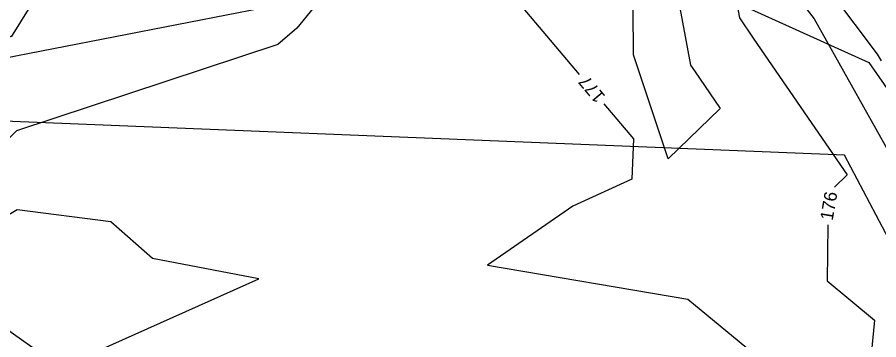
# Model space of a CAD drawing. Extents: x 2086416 to 2115205, y 575507 to 632762.
# Drawn here: x 2111423.3 to 2111557.3, y 581547.6 to 581597.8 of the extents above; entities that cross this region are included whole.
import ezdxf

# ---------------------------------------------------------------- set-up
doc = ezdxf.new("R2010")
doc.units = 0
for name, color, linetype in [('DTM Contours Major', 7, 'Continuous'), ('DTM Contours Minor', 7, 'Continuous'), ('DTM Contours Minor Text', 7, 'Continuous'), ('Exist Hydrographic FEMA Cross Section', 7, 'Continuous'), ('Exist Vegetation Woods Line', 7, 'Continuous')]:
    doc.layers.add(name, color=color, linetype=linetype)

msp = doc.modelspace()

# ---------------------------------------------------------------- linework, layer by layer
at = {"layer": 'DTM Contours Major'}
msp.add_lwpolyline([(2111534.94, 581633.7), (2111534.95, 581633.69), (2111540.69, 581621.59), (2111540.75, 581620.7), (2111543.07, 581605.02), (2111543.15, 581604.73), (2111546.21, 581598.92), (2111547.25, 581597.53), (2111560.71, 581573.54), (2111564.82, 581569.8), (2111569.33, 581557.68), (2111570.48, 581553.11), (2111574.03, 581543.19)], dxfattribs=at)
at = {"layer": 'DTM Contours Minor'}
for points in [[(2111512.9, 581612.94), (2111502.54, 581616.24), (2111495.93, 581612.32), (2111495.05, 581609.68), (2111493.14, 581612.37), (2111486.49, 581613.5), (2111483.67, 581613.74), (2111483.2, 581613.6), (2111482.12, 581613.44), (2111472.63, 581599.99), (2111469.34, 581599.17), (2111466.84, 581596.07), (2111463.88, 581593.54), (2111423.2, 581580.1), (2111421.17, 581578.02), (2111413.92, 581573.83), (2111415.71, 581582.77), (2111413.83, 581586.35), (2111407.09, 581599.12), (2111404.08, 581600.93), (2111385.48, 581590.71), (2111395.03, 581602.54), (2111389.52, 581602.88), (2111380.32, 581601.49)], [(2111438.65, 581609.75), (2111436.08, 581609.42), (2111428.87, 581608.47), (2111427.89, 581607.98), (2111428.68, 581604.78), (2111428.43, 581604.52), (2111422.37, 581594.71), (2111411.16, 581598.81), (2111409.52, 581598.94), (2111408.82, 581600.27), (2111408.4, 581601.08), (2111407.65, 581601.53), (2111399, 581606.02), (2111389.75, 581605.28), (2111373.81, 581602.89), (2111368.57, 581602.56), (2111362.09, 581601.98), (2111346.11, 581598.33)], [(2111496.29, 581605.95), (2111510.71, 581588.87)], [(2111525.13, 581605.96), (2111528.05, 581590.31), (2111528.67, 581589.4), (2111532.67, 581583.57), (2111524.59, 581575.75), (2111519.16, 581591.92), (2111519.09, 581606.16)], [(2111534.22, 581605.33), (2111535.65, 581597.66), (2111537.91, 581594.37), (2111552.42, 581573.24), (2111550.43, 581571.32)], [(2111549.98, 581601.49), (2111557.09, 581592.02), (2111557.69, 581590.96)], [(2111514.58, 581584.29), (2111519.19, 581578.84), (2111518.93, 581572.6), (2111509.75, 581568.35), (2111496.49, 581559.18), (2111527.62, 581553.93), (2111538.57, 581544.91), (2111535.36, 581512.4), (2111530.44, 581501.65), (2111545.28, 581484.15), (2111544.79, 581497.77), (2111547.82, 581496.57), (2111551.06, 581478.3), (2111550.44, 581473.33), (2111552.13, 581466.8)], [(2111460.9, 581557.08), (2111444.39, 581560.24), (2111437.91, 581565.95), (2111423.3, 581567.8), (2111420.16, 581565.92), (2111420.73, 581560.08), (2111419.75, 581556.92)], [(2111549.42, 581565.48), (2111549.3, 581556.75), (2111556.68, 581550.67), (2111555.04, 581534.11), (2111575.11, 581516.45), (2111580.14, 581502.39), (2111580.74, 581501.15), (2111583.03, 581497), (2111577.68, 581466.9), (2111605.74, 581475), (2111607.43, 581474.14), (2111607.69, 581473.21), (2111591.9, 581421.84), (2111590.92, 581419.37), (2111591.04, 581419.17), (2111590.97, 581419.11)], [(2111418.62, 581551.41), (2111426.83, 581545.6), (2111432.28, 581544.28), (2111460.9, 581557.08)]]:
    msp.add_lwpolyline(points, dxfattribs=at)
at = {"layer": 'Exist Hydrographic FEMA Cross Section'}
msp.add_lwpolyline([(2111658.78, 581615.59), (2111477.28, 581602.23), (2111476.99, 581602.18), (2111467.38, 581600.31), (2111457.77, 581598.44), (2111448.17, 581596.57), (2111438.56, 581594.71), (2111428.95, 581592.84), (2111419.34, 581590.97), (2111409.73, 581589.1), (2111400.13, 581587.23), (2111390.52, 581585.36), (2111380.91, 581583.5), (2111371.31, 581581.63), (2111361.7, 581579.76), (2111352.09, 581577.89)], dxfattribs=at)
at = {"layer": 'Exist Vegetation Woods Line'}
for points in [[(2111257.87, 581581.4), (2111333.1, 581590.97), (2111406.18, 581600.07), (2111473.94, 581614.42), (2111501.63, 581613.42), (2111525.04, 581604.65), (2111555.79, 581590.73), (2111597.41, 581531.02), (2111635.4, 581485.12), (2111692.38, 581438.81), (2111736.92, 581397.7), (2111757.96, 581379.06)], [(2111566.76, 581548.29), (2111551.99, 581576.31), (2111385.4, 581583.05), (2111297.09, 581569.27), (2111253.55, 581562.72), (2111242.01, 581577.17), (2111257.87, 581581.4)]]:
    msp.add_lwpolyline(points, dxfattribs=at)

# ---------------------------------------------------------------- texts
at = {"layer": 'DTM Contours Minor Text'}
for s, rotation, p in [('177', 130.1804, (2111514.88, 581585.49)), ('176', 80.2052, (2111550.15, 581566.05))]:
    msp.add_text(s, height=2, rotation=rotation, dxfattribs=at).set_placement(p)

doc.saveas('drawing.dxf')
